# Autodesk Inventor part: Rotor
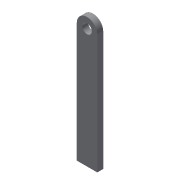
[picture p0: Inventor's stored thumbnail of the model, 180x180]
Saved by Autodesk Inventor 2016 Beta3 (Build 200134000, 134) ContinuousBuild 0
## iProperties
Created: 2016-03
Part Number: Rotor
Material: Generic
Document SubType Name: Modeling
Designer: Gaurav
Density: 1 g/cm^3
Appearance: Default
Author: Gaurav
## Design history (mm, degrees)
sketch "Sketch1"
  geometry: L1 (2.143, 0)-(2.143, -33.249); L2 (2.143, -33.249)-(-2.143, -33.249); L3 (-2.143, -33.249)-(-2.143, 0); C1 r 1 at (0, 0); A1 r 2.143 centre (0, 0) between (2.143, 0) and (-2.143, 0); 1 further point
  constraints: 6 end point, 2 centre point, 2 coincident, 2 point on circle, 1 perpendicular, 1 tangent, 1 vertical
  dimensions: "d0" = 2 diameter of C1
extrude "Extrusion1" new body sketch "Sketch1" distance "d1" = 2.5; taper "d2" = 0 deg
node "Direct Edit1"
body "Solid1"
move_body "Move1" dims "d5" = -8.25
move_body "Move2" dims "d8" = -1.25
other parameters: "d3" = 0, "d4" = 0, "d6" = 0, "d7" = 0
